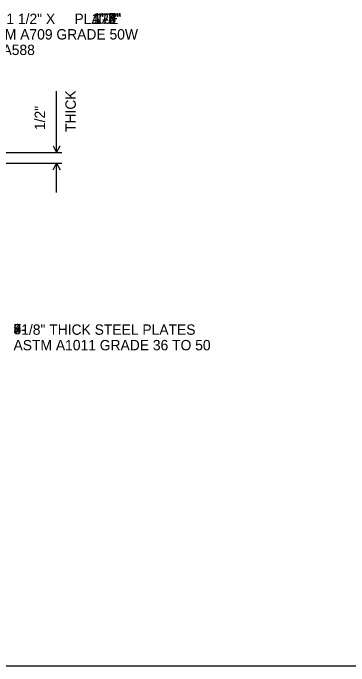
# Model space of a CAD drawing. Extents: x 997.7 to 1009.7, y 1494.3 to 1503.3.
# Drawn here: x 1002.464 to 1003.815, y 1495.626 to 1498.254 of the extents above; entities that cross this region are included whole.
import ezdxf

# ---------------------------------------------------------------- set-up
doc = ezdxf.new("R2010")
doc.units = 0
for name, color, linetype in [('Level 1', 7, 'Continuous'), ('Level 10', 7, 'Continuous'), ('Level 11', 7, 'Continuous'), ('Level 12', 7, 'Continuous'), ('Level 13', 7, 'Continuous'), ('Level 14', 7, 'Continuous'), ('Level 2', 7, 'Continuous'), ('Level 9', 7, 'Continuous')]:
    doc.layers.add(name, color=color, linetype=linetype)

msp = doc.modelspace()

# ---------------------------------------------------------------- linework, layer by layer
at = {"layer": 'Level 1'}
msp.add_line((998.7369, 1495.6261), (1009.1944, 1495.6261), dxfattribs=at)
at = {"layer": 'Level 2'}
for p, q in [((1002.639, 1497.6922), (1002.639, 1497.9404)), ((1002.1914, 1497.6922), (1002.6603, 1497.6922)), ((1002.1914, 1497.6505), (1002.6603, 1497.6505)), ((1002.639, 1497.5325), (1002.639, 1497.6505))]:
    msp.add_line(p, q, dxfattribs=at)
for points in [[(1002.6251, 1497.7199), (1002.639, 1497.6922), (1002.6529, 1497.7199)], [(1002.6251, 1497.6228), (1002.639, 1497.6505), (1002.6529, 1497.6228)]]:
    msp.add_lwpolyline(points, dxfattribs=at)

# ---------------------------------------------------------------- texts
at = {"layer": 'Level 10'}
for s, p in [('12"', (1002.7872, 1498.211)), ('5-', (1002.4648, 1496.961))]:
    msp.add_text(s, height=0.04167, dxfattribs=at).set_placement(p)
at = {"layer": 'Level 11'}
for s, p in [('1\'-2"', (1002.7883, 1498.2103)), ('6-', (1002.4655, 1496.961))]:
    msp.add_text(s, height=0.04167, dxfattribs=at).set_placement(p)
at = {"layer": 'Level 12'}
for s, p in [('1\'-4"', (1002.7867, 1498.2113)), ('7-', (1002.4655, 1496.9611))]:
    msp.add_text(s, height=0.04167, dxfattribs=at).set_placement(p)
at = {"layer": 'Level 13'}
for s, p in [('1\'-5"', (1002.7864, 1498.2125)), ('8-', (1002.4655, 1496.9612))]:
    msp.add_text(s, height=0.04167, dxfattribs=at).set_placement(p)
at = {"layer": 'Level 14'}
for s, p in [('1\'-7"', (1002.7802, 1498.2107)), ('9-', (1002.4653, 1496.9608))]:
    msp.add_text(s, height=0.04167, dxfattribs=at).set_placement(p)
at = {"layer": 'Level 2'}
for s, height, p in [('    X 1 1/2" X     PLATE', 0.041667, (1002.3221, 1498.2102)), ('ASTM A709 GRADE 50W', 0.041667, (1002.3221, 1498.1477)), ('OR A588', 0.04167, (1002.3221, 1498.0852)), ('  1/8" THICK STEEL PLATES', 0.041667, (1002.4655, 1496.9591)), ('ASTM A1011 GRADE 36 TO 50', 0.041667, (1002.4655, 1496.8966))]:
    msp.add_text(s, height=height, dxfattribs=at).set_placement(p)
for s, p in [('THICK', (1002.716, 1497.7756)), ('1/2"', (1002.592, 1497.7833))]:
    msp.add_text(s, height=0.04167, rotation=90, dxfattribs=at).set_placement(p)
at = {"layer": 'Level 9'}
for s, p in [('10"', (1002.7967, 1498.211)), ('4-', (1002.4655, 1496.9606))]:
    msp.add_text(s, height=0.04167, dxfattribs=at).set_placement(p)

doc.saveas('drawing.dxf')
